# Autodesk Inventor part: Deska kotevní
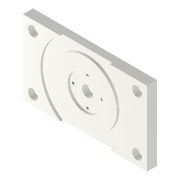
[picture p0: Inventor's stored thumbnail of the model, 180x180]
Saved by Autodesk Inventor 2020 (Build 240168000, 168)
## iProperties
Created: 2025-03
Part Number: Deska kotevní
Material: Ocel
Document SubType Name: Modeling
Designer: doma
Density: 7.85 g/cm^3
Appearance: Ocel
Mass: 5075.73 g
Surface Area: 988.913 cm^2
Volume: 646.589 cm^3
Author: doma
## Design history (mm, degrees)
sketch "Náčrt1"
  geometry: L1 (-125, -75)-(125, -75); L2 (125, -75)-(125, 75); L3 (125, 75)-(-125, 75); L4 (-125, 75)-(-125, -75); L5 (-125, -75)-(125, 75); L6 (125, -75)-(-125, 75); 1 further point
  constraints: 12 end point, 2 midpoint, 2 parallel, 1 horizontal, 1 perpendicular
  dimensions: "d0" = 250 distance of L3.end L2.end; "d1" = 150 distance of L2.end L1.end
extrude "Vysunutí1" new body sketch "Náčrt1" distance "d2" = 20; taper "d3" = 0 deg
sketch "Náčrt2"
  geometry: C1 r 64 at (0, 0); C2 r 90 at (0, 0); 1 further point
  constraints: 2 centre point, 2 coincident
  dimensions: "d4" = 128 diameter of C1; "d5" = 180 diameter of C2
extrude "Vysunutí2" cut sketch "Náčrt2" distance "d6" = 5; taper "d7" = 0 deg
sketch "Náčrt3"
  geometry: C1 r 35 at (0, 0); 1 further point
  constraints: 1 centre point, 1 coincident
  dimensions: "d8" = 70 diameter of C1
extrude "Vysunutí3" cut sketch "Náčrt3" distance "d9" = 5; taper "d10" = 0 deg
sketch "Náčrt4"
  geometry: C1 r 11 at (0, 0); 1 further point
  constraints: 1 centre point, 1 coincident
  dimensions: "d11" = 22 diameter of C1
extrude "Vysunutí4" cut sketch "Náčrt4" extent not by distance; stored distance "d12" = 0; taper "d13" = 0 deg
sketch "Náčrt5"
  geometry: 5 further points
  constraints: 5 other
  dimensions: "d14" = 29 distance of point (0, 0) point (0, 29); "d19" = 360 deg dimension on point (0, 0) point (0, 29) (derived)
hole "Díra1" sketch "Náčrt5" at (0, 29), (-29, 0), (0, -29), (29, 0) diameter "d21" = 4.917; stored, may be unused: countersink angle "d25" = 90 deg, drill point angle "d27" = 118 deg; dims "d22" = 12, "d23" = 4, "d24" = 2, "d26" = 17.1
sketch "Náčrt6"
  geometry: L1 (-125, 75)-(-125, -75) reference; L2 (-49.749, 75)-(-125, 75) reference; 5 further points
  constraints: 1 horizontal, 1 vertical, 3 other
  dimensions: "d28" = 20 distance from line of point (-105, 55) L1; "d29" = 20 distance from line of L2 point (-105, 55); "d32" = 210 distance of point (-105, 55) point (105, 55); "d35" = 110 distance of point (-105, 55) point (-105, -55)
hole "Díra2" sketch "Náčrt6" at (-105, 55), (105, 55), (-105, -55), (105, -55) diameter "d38" = 13.5; stored, may be unused: countersink angle "d42" = 90 deg, drill point angle "d44" = 118 deg; dims "d39" = 15, "d40" = 20, "d41" = 12, "d43" = 20
sketch "Náčrt7"
  geometry: C1 r 17.5 at (0, 0); 1 further point
  constraints: 1 centre point, 1 coincident
  dimensions: "d45" = 35 diameter of C1
extrude "Vysunutí5" cut sketch "Náčrt7" distance "d46" = 3; taper "d47" = 0 deg
node "Těleso1"
